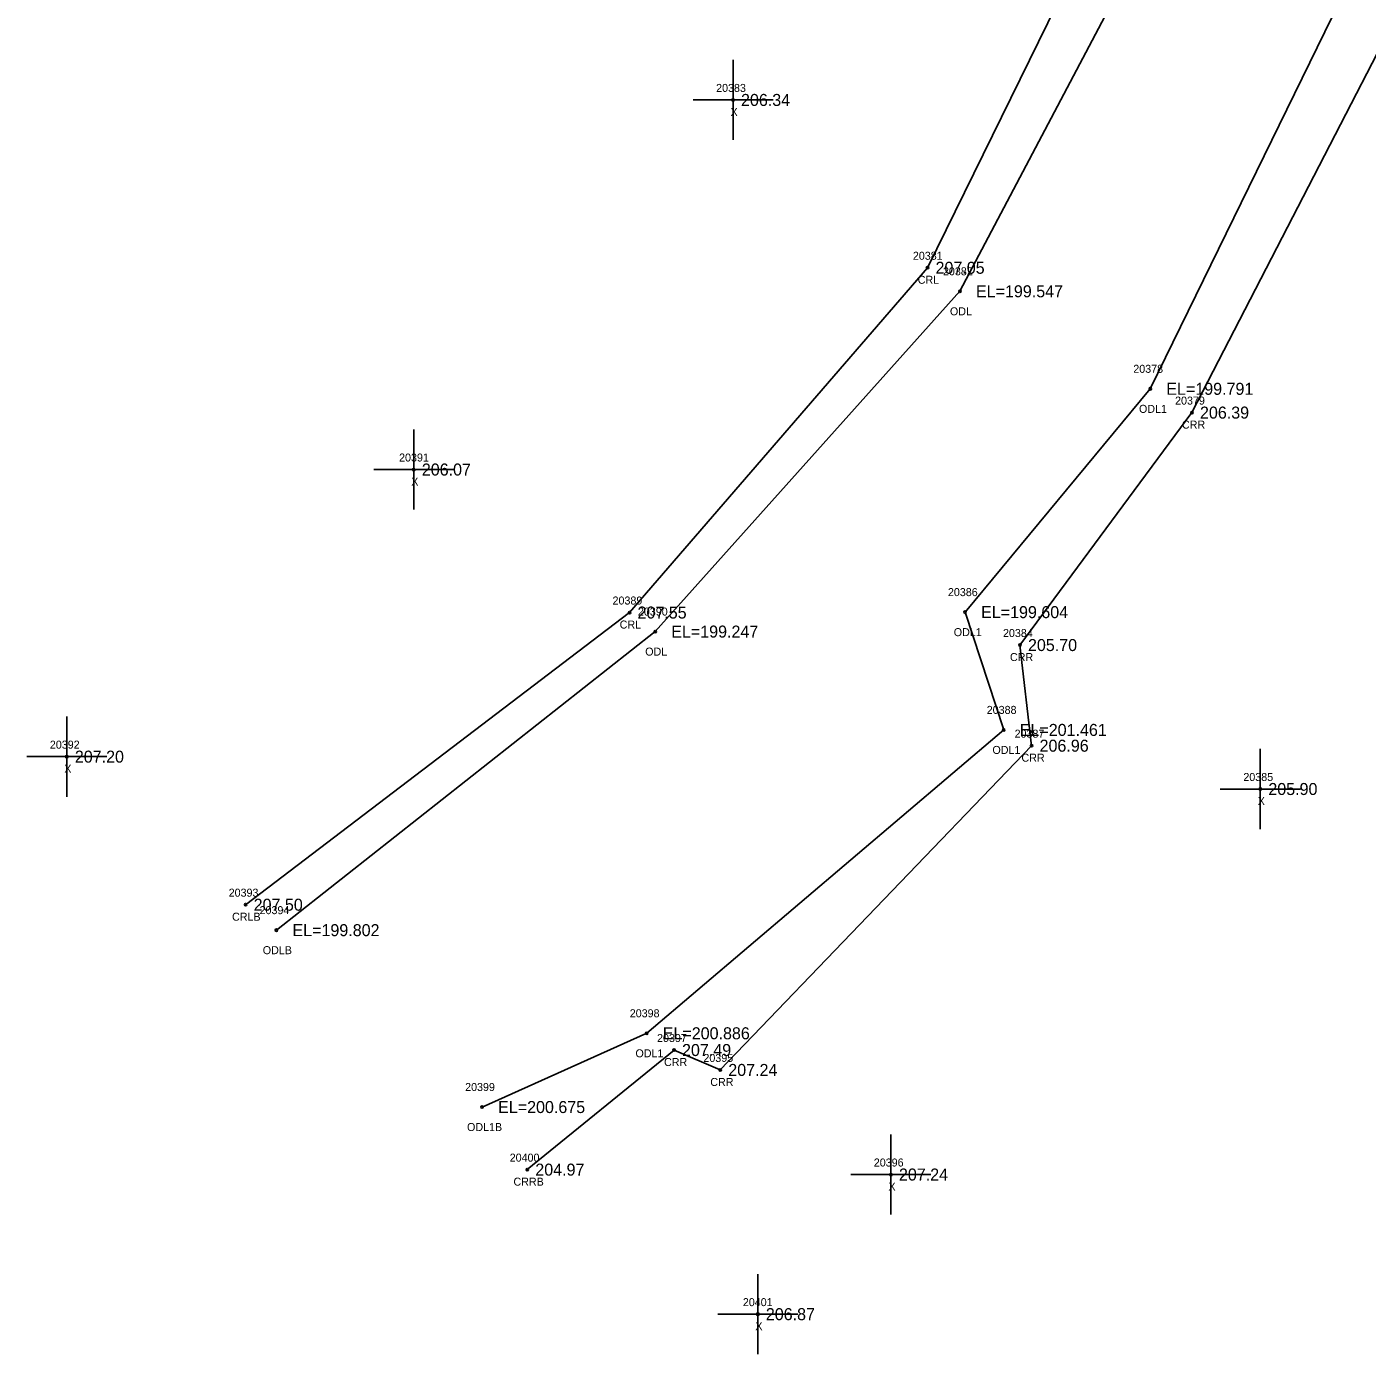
# Model space of a CAD drawing. Extents: x 2260230 to 2261304, y 1064626 to 1065587.
# Drawn here: x 2260460.8 to 2260628.3, y 1064626.3 to 1064792 of the extents above; entities that cross this region are included whole.
import ezdxf

# ---------------------------------------------------------------- set-up
doc = ezdxf.new("R2010")
doc.units = 0
for name, color, linetype in [('RD_EX_H2O', 7, 'Continuous'), ('RD_EX_H2O_txCode', 7, 'Continuous'), ('RD_EX_Misc', 7, 'Continuous'), ('RD_EX_Misc_txCode', 7, 'Continuous'), ('RD_EX_TX_H2O_ELEV', 7, 'Continuous'), ('RD_EX_TX_Misc_ELEV', 7, 'Continuous'), ('RD_SMD_Locator', 7, 'Continuous')]:
    doc.layers.add(name, color=color, linetype=linetype)

msp = doc.modelspace()

# ---------------------------------------------------------------- linework, layer by layer
at = {"layer": 'RD_EX_H2O'}
for points in [[(2260766.96, 1065089.79), (2260769.94, 1065084.22), (2260769.59, 1065075.21), (2260766.59, 1065063.56), (2260718.2, 1065001.51), (2260666.03, 1064928.94), (2260617.31, 1064851.47), (2260573.34, 1064761.94), (2260536.11, 1064718.88), (2260488.15, 1064682.39)], [(2260772.5, 1065076.18), (2260769.88, 1065063.47), (2260720.95, 1064998.76), (2260670.41, 1064924.84), (2260623.49, 1064846.38), (2260577.39, 1064759), (2260539.32, 1064716.5), (2260492, 1064679.21)], [(2260814.11, 1065053.05), (2260812.59, 1065051.01), (2260806.25, 1065051.8), (2260750.48, 1064985.06), (2260697.06, 1064907.27), (2260648.8, 1064826.07), (2260606.38, 1064743.85), (2260584.89, 1064714.82), (2260586.34, 1064702.25), (2260547.45, 1064661.75), (2260541.67, 1064664.24), (2260523.34, 1064649.3)], [(2260798.69, 1065050.24), (2260747.43, 1064987.58), (2260691.08, 1064910.92), (2260641.97, 1064830.24), (2260601.17, 1064746.82), (2260578.03, 1064718.93), (2260582.86, 1064704.22), (2260538.26, 1064666.33), (2260517.69, 1064657.12)]]:
    msp.add_lwpolyline(points, dxfattribs=at)
at = {"layer": 'RD_EX_Misc'}
for p, q in [((2260549.04, 1064777.9), (2260549.04, 1064787.9)), ((2260544.04, 1064782.9), (2260554.04, 1064782.9)), ((2260509.16, 1064731.74), (2260509.16, 1064741.74)), ((2260504.16, 1064736.74), (2260514.16, 1064736.74)), ((2260465.81, 1064695.88), (2260465.81, 1064705.88)), ((2260614.92, 1064691.84), (2260614.92, 1064701.84)), ((2260460.81, 1064700.88), (2260470.81, 1064700.88)), ((2260609.92, 1064696.84), (2260619.92, 1064696.84)), ((2260568.77, 1064643.69), (2260568.77, 1064653.69)), ((2260563.77, 1064648.69), (2260573.77, 1064648.69)), ((2260552.14, 1064626.25), (2260552.14, 1064636.25)), ((2260547.14, 1064631.25), (2260557.14, 1064631.25))]:
    msp.add_line(p, q, dxfattribs=at)
at = {"layer": 'RD_SMD_Locator'}
for centre in [(2260549.04, 1064782.9), (2260573.34, 1064761.94), (2260577.39, 1064759), (2260601.17, 1064746.82), (2260606.38, 1064743.85), (2260509.16, 1064736.74), (2260536.11, 1064718.88), (2260578.03, 1064718.93), (2260539.32, 1064716.5), (2260584.89, 1064714.82), (2260582.86, 1064704.22), (2260586.34, 1064702.25), (2260465.81, 1064700.88), (2260614.92, 1064696.84), (2260488.15, 1064682.39), (2260492, 1064679.21), (2260538.26, 1064666.33), (2260541.67, 1064664.24), (2260547.45, 1064661.75), (2260517.69, 1064657.12), (2260523.34, 1064649.3), (2260568.77, 1064648.69), (2260552.14, 1064631.25)]:
    msp.add_circle(centre, 0.15, dxfattribs=at)

# ---------------------------------------------------------------- texts
at = {"layer": 'RD_EX_H2O_txCode'}
for s, p in [('20381', (2260571.51, 1064762.94)), ('20382', (2260575.27, 1064761)), ('CRL', (2260572.12, 1064759.94)), ('ODL', (2260576.14, 1064756)), ('20378', (2260599.05, 1064748.82)), ('ODL1', (2260599.76, 1064743.82)), ('20379', (2260604.27, 1064744.85)), ('CRR', (2260605.13, 1064741.85)), ('20386', (2260575.89, 1064720.93)), ('20389', (2260533.99, 1064719.88)), ('20390', (2260537.16, 1064718.5)), ('CRL', (2260534.88, 1064716.88)), ('ODL1', (2260576.62, 1064715.93)), ('20384', (2260582.77, 1064715.82)), ('ODL', (2260538.07, 1064713.5)), ('CRR', (2260583.64, 1064712.82)), ('20388', (2260580.74, 1064706.22)), ('20387', (2260584.22, 1064703.25)), ('ODL1', (2260581.45, 1064701.22)), ('CRR', (2260585.08, 1064700.25)), ('20393', (2260486.03, 1064683.39)), ('CRLB', (2260486.45, 1064680.39)), ('20394', (2260489.89, 1064681.21)), ('ODLB', (2260490.29, 1064676.21)), ('20398', (2260536.14, 1064668.33)), ('20397', (2260539.55, 1064665.24)), ('ODL1', (2260536.85, 1064663.33)), ('CRR', (2260540.42, 1064662.24)), ('20395', (2260545.34, 1064662.75)), ('20399', (2260515.57, 1064659.12)), ('CRR', (2260546.2, 1064659.75)), ('ODL1B', (2260515.81, 1064654.12)), ('20400', (2260521.14, 1064650.3)), ('CRRB', (2260521.61, 1064647.3))]:
    msp.add_text(s, height=1, dxfattribs=at).set_placement(p)
at = {"layer": 'RD_EX_Misc_txCode'}
for s, p in [('20383', (2260546.93, 1064783.9)), ('X', (2260548.73, 1064780.9)), ('20391', (2260507.32, 1064737.74)), ('X', (2260508.84, 1064734.74)), ('20392', (2260463.69, 1064701.88)), ('X', (2260465.49, 1064698.88)), ('20385', (2260612.8, 1064697.84)), ('X', (2260614.6, 1064694.84)), ('20396', (2260566.63, 1064649.69)), ('X', (2260568.46, 1064646.69)), ('20401', (2260550.27, 1064632.25)), ('X', (2260551.83, 1064629.25))]:
    msp.add_text(s, height=1, dxfattribs=at).set_placement(p)
at = {"layer": 'RD_EX_TX_H2O_ELEV'}
for s, p in [('207.05', (2260574.34, 1064761.19)), ('EL=199.547', (2260579.39, 1064758.25)), ('EL=199.791', (2260603.17, 1064746.07)), ('206.39', (2260607.38, 1064743.1)), ('EL=199.604', (2260580.03, 1064718.18)), ('207.55', (2260537.11, 1064718.13)), ('EL=199.247', (2260541.32, 1064715.75)), ('205.70', (2260585.89, 1064714.07)), ('EL=201.461', (2260584.86, 1064703.47)), ('206.96', (2260587.34, 1064701.5)), ('207.50', (2260489.15, 1064681.64)), ('EL=199.802', (2260494, 1064678.46)), ('EL=200.886', (2260540.26, 1064665.58)), ('207.49', (2260542.67, 1064663.49)), ('207.24', (2260548.45, 1064661)), ('EL=200.675', (2260519.69, 1064656.37)), ('204.97', (2260524.34, 1064648.55))]:
    msp.add_text(s, height=1.5, dxfattribs=at).set_placement(p)
at = {"layer": 'RD_EX_TX_Misc_ELEV'}
for s, p in [('206.34', (2260550.04, 1064782.15)), ('206.07', (2260510.16, 1064735.99)), ('207.20', (2260466.81, 1064700.13)), ('205.90', (2260615.92, 1064696.09)), ('207.24', (2260569.77, 1064647.94)), ('206.87', (2260553.14, 1064630.5))]:
    msp.add_text(s, height=1.5, dxfattribs=at).set_placement(p)

doc.saveas('drawing.dxf')
